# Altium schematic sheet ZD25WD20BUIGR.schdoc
size 127 x 101 mm
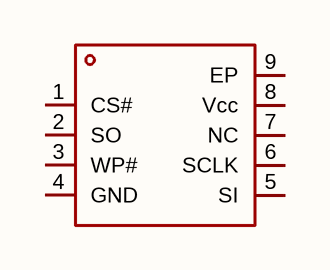
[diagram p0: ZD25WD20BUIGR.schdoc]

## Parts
U?  zd25wd20buigr  [USON-8_L3.0-W2.0-P0.50-BL-EP_ZD25XX]  (value not drawn)

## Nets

Not connected (* = marked no-connect by the designer): U? 1(CS#) 2(SO) 3(WP#) 4(GND) 5(SI) 6(SCLK) 7(NC) 8(Vcc) 9(EP)

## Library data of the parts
U? = zd25wd20buigr: 接口类型:SPI;存储容量:2Mbit;时钟频率(fc):104MHz;; Manufacturer: Zetta(澜智); AddInBom: yes; ModelId: 12a239e5c7384371915ecb51201bf581; ModelName: USON-8_L3.0-W2.0-H0.6-P0.50; ModelTransform: 118.8974,78.74,0,90,0,0,0,0,0; Interface: SPI; Memory Size: 2Mbit; Clock Frequency: 104MHz; Voltage - Supply: 1.65V~3.6V; Program / Erase Cycles: 100000次; Page Programming Time (Tpp): 2ms; Block Erase Time(tBE): 10ms@(64KB); Data Retention - TDR (Year): 20年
